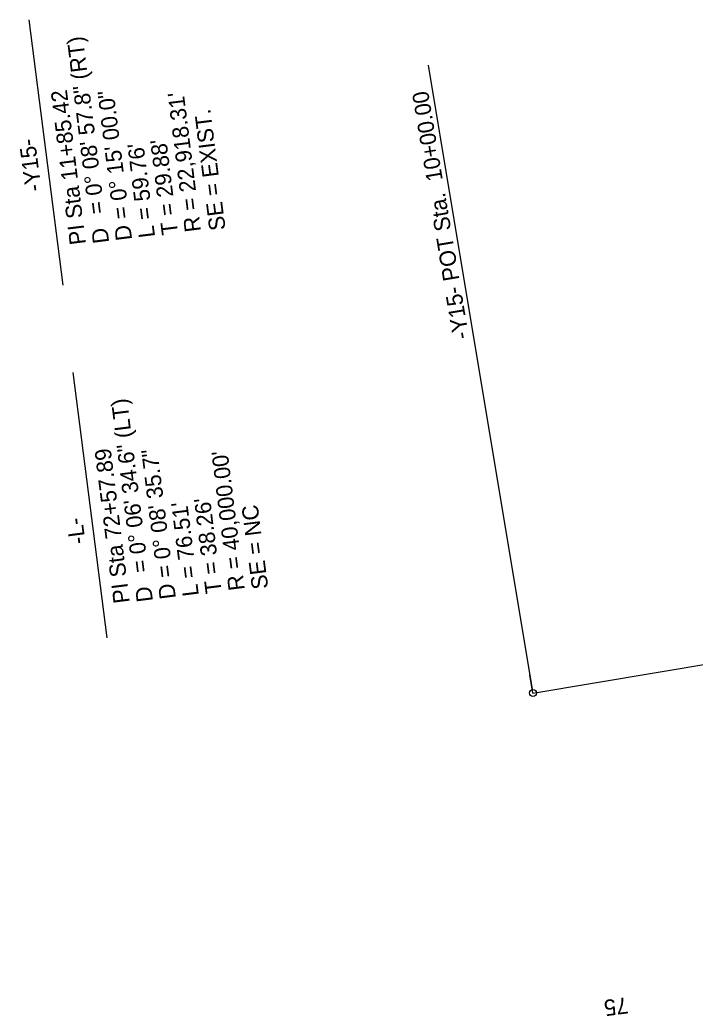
# Model space of a CAD drawing. Extents: x 2367848 to 2369479, y 800728 to 808616.
# Drawn here: x 2367847.8 to 2368139.6, y 807759.5 to 808189.9 of the extents above; entities that cross this region are included whole.
import ezdxf

# ---------------------------------------------------------------- set-up
doc = ezdxf.new("R2010")
doc.units = 0
for name, color, linetype in [('Prop Horizontal Alignment', 7, 'Continuous'), ('Prop Horizontal Alignment Curve and Spiral Data', 7, 'Continuous'), ('Prop Horizontal Alignment Station Label', 7, 'Continuous'), ('Prop Horizontal Alignment Tick Label', 7, 'Continuous'), ('Prop Horizontal Alignment Tick Large', 7, 'Continuous')]:
    doc.layers.add(name, color=color, linetype=linetype)

msp = doc.modelspace()

# ---------------------------------------------------------------- linework, layer by layer
at = {"layer": 'Prop Horizontal Alignment'}
msp.add_line((2368069.53, 807899.08), (2368222.95, 807924.63), dxfattribs=at)
at = {"layer": 'Prop Horizontal Alignment Station Label'}
for p, q in [((2367866.49, 808075.25), (2367851.85, 808189.87)), ((2368069.28, 807900.56), (2368024.36, 808170.35)), ((2367885.48, 807922.9), (2367870.84, 808037.52))]:
    msp.add_line(p, q, dxfattribs=at)
msp.add_circle((2368069.53, 807899.08), 1.5, dxfattribs=at)
at = {"layer": 'Prop Horizontal Alignment Tick Large'}
msp.add_line((2368069.53, 807899.08), (2368068.21, 807906.98), dxfattribs=at)

# ---------------------------------------------------------------- texts
at = {"layer": 'Prop Horizontal Alignment Curve and Spiral Data'}
for s, rotation, p in [('= 0%%d 08\' 57.8" (RT)', 97.1063, (2367884.52, 808106.42)), ('PI Sta 11+85.42', 97.1063, (2367876.39, 808093.13)), ('D = 0%%d 15\' 00.0"', 97.1063, (2367896.32, 808094.94)), ("R = 22,918.31'", 97.1063, (2367926.09, 808098.65)), ('SE = EXIST.', 97.2784, (2367936.73, 808099.32)), ('-Y15-', 97.4901, (2367857.23, 808116.17)), ("T = 29.88'", 97.1063, (2367916.17, 808097.41)), ("L = 59.76'", 97.1063, (2367906.24, 808096.18)), ('D', 97.1063, (2367886.4, 808093.7)), ('= 0%%d 06\' 34.6" (LT)', 97.1063, (2367903.43, 807951.51)), ('PI Sta 72+57.89', 97.1063, (2367895.31, 807938.23)), ('D = 0%%d 08\' 35.7"', 97.1063, (2367915.24, 807940.04)), ("R = 40,000.00'", 97.1063, (2367945.01, 807943.75)), ("T = 38.26'", 97.1063, (2367935.09, 807942.51)), ("L = 76.51'", 97.1063, (2367925.16, 807941.27)), ('SE = NC', 97.2784, (2367955.15, 807944.38)), ('-L-', 97.4901, (2367876.22, 807963.82)), ('D', 97.1063, (2367905.32, 807938.8))]:
    msp.add_text(s, height=7, rotation=rotation, dxfattribs=at).set_placement(p)
at = {"layer": 'Prop Horizontal Alignment Station Label'}
msp.add_text('-Y15- POT Sta.  10+00.00', height=7, rotation=99.4533, dxfattribs=at).set_placement((2368041.96, 808052.5))
at = {"layer": 'Prop Horizontal Alignment Tick Label'}
msp.add_text('75', height=7, rotation=187.418, dxfattribs=at).set_placement((2368110.16, 807767.7))

doc.saveas('drawing.dxf')
